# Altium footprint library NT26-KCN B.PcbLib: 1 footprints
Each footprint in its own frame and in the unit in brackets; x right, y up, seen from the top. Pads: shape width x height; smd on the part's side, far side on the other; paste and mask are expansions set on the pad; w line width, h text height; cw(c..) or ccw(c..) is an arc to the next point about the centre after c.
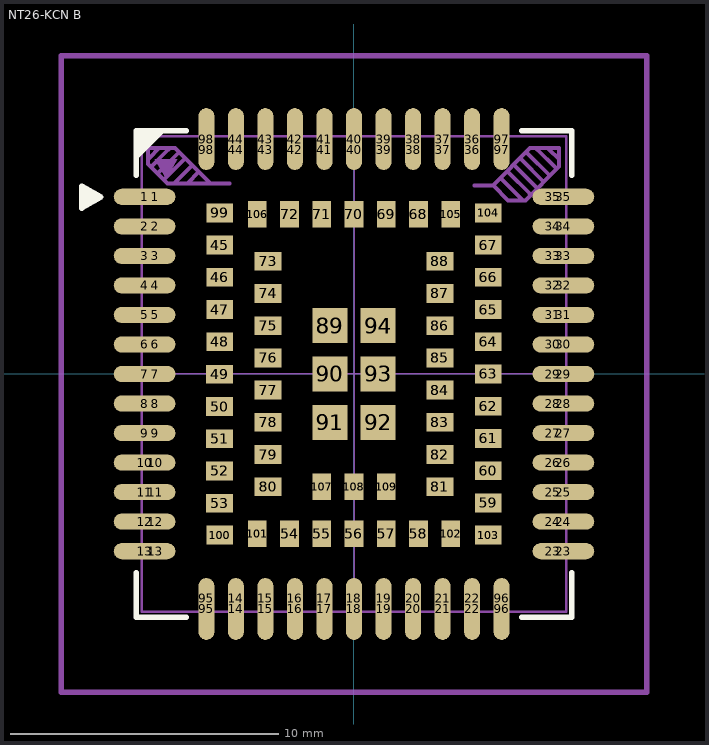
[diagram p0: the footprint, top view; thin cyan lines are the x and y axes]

## NT26-KCN B [mm]
height 2.54
pads (220):
  oval 2.3x0.6 smd mask+0.076: 1(-7.8,6.6) 2(-7.8,5.5) 3(-7.8,4.4) 4(-7.8,3.3) 5(-7.8,2.2) 6(-7.8,1.1) 7(-7.8,0) 8(-7.8,-1.1) 9(-7.8,-2.2) 10(-7.8,-3.3) 11(-7.8,-4.4) 12(-7.8,-5.5) 13(-7.8,-6.6) 23(7.8,-6.6) 24(7.8,-5.5) 25(7.8,-4.4) 26(7.8,-3.3) 27(7.8,-2.2) 28(7.8,-1.1) 29(7.8,0) 30(7.8,1.1) 31(7.8,2.2) 32(7.8,3.3) 33(7.8,4.4) 34(7.8,5.5) 35(7.8,6.6)
  oval 1.5x0.6 on Mech1 mask+0.076: 1(-7.4,6.6) 2(-7.4,5.5) 3(-7.4,4.4) 4(-7.4,3.3) 5(-7.4,2.2) 6(-7.4,1.1) 7(-7.4,0) 8(-7.4,-1.1) 9(-7.4,-2.2) 10(-7.4,-3.3) 11(-7.4,-4.4) 12(-7.4,-5.5) 13(-7.4,-6.6) 23(7.4,-6.6) 24(7.4,-5.5) 25(7.4,-4.4) 26(7.4,-3.3) 27(7.4,-2.2) 28(7.4,-1.1) 29(7.4,0) 30(7.4,1.1) 31(7.4,2.2) 32(7.4,3.3) 33(7.4,4.4) 34(7.4,5.5) 35(7.4,6.6)
  oval 0.6x2.3 smd mask+0.076: 14(-4.4,-8.75) 15(-3.3,-8.75) 16(-2.2,-8.75) 17(-1.1,-8.75) 18(0,-8.75) 19(1.1,-8.75) 20(2.2,-8.75) 21(3.3,-8.75) 22(4.4,-8.75) 36(4.4,8.75) 37(3.3,8.75) 38(2.2,8.75) 39(1.1,8.75) 40(0,8.75) 41(-1.1,8.75) 42(-2.2,8.75) 43(-3.3,8.75) 44(-4.4,8.75) 95(-5.5,-8.75) 96(5.5,-8.75) 97(5.5,8.75) 98(-5.5,8.75)
  oval 0.6x1.5 on Mech1 mask+0.076: 14(-4.4,-8.35) 15(-3.3,-8.35) 16(-2.2,-8.35) 17(-1.1,-8.35) 18(0,-8.35) 19(1.1,-8.35) 20(2.2,-8.35) 21(3.3,-8.35) 22(4.4,-8.35) 36(4.4,8.35) 37(3.3,8.35) 38(2.2,8.35) 39(1.1,8.35) 40(0,8.35) 41(-1.1,8.35) 42(-2.2,8.35) 43(-3.3,8.35) 44(-4.4,8.35) 95(-5.5,-8.35) 96(5.5,-8.35) 97(5.5,8.35) 98(-5.5,8.35)
  rect 1x0.7 smd: 45(-5,4.8) 46(-5,3.6) 47(-5,2.4) 48(-5,1.2) 49(-5.003,-0.011) 50(-5.003,-1.211) 51(-5.003,-2.411) 52(-5.003,-3.611) 53(-5.003,-4.811) 59(5,-4.8) 60(5,-3.6) 61(5,-2.4) 62(5,-1.2) 63(5,0) 64(5,1.2) 65(5,2.4) 66(5,3.6) 67(5,4.8) 73(-3.2,4.2) 74(-3.2,3) 75(-3.2,1.8) 76(-3.2,0.6) 77(-3.2,-0.6) 78(-3.2,-1.8) 79(-3.2,-3) 80(-3.2,-4.2) 81(3.2,-4.2) 82(3.2,-3) 83(3.2,-1.8) 84(3.2,-0.6) 85(3.2,0.6) 86(3.2,1.8) 87(3.2,3) 88(3.2,4.2) 99(-5,6) 100(-5,-6) 103(5,-6) 104(5,6)
  rect 1x0.7 on Mech1: 45(-5,4.8) 46(-5,3.6) 47(-5,2.4) 48(-5,1.2) 49(-5.003,-0.011) 50(-5.003,-1.211) 51(-5.003,-2.411) 52(-5.003,-3.611) 53(-5.003,-4.811) 59(5,-4.8) 60(5,-3.6) 61(5,-2.4) 62(5,-1.2) 63(5,0) 64(5,1.2) 65(5,2.4) 66(5,3.6) 67(5,4.8) 73(-3.2,4.2) 74(-3.2,3) 75(-3.2,1.8) 76(-3.2,0.6) 77(-3.2,-0.6) 78(-3.2,-1.8) 79(-3.2,-3) 80(-3.2,-4.2) 81(3.2,-4.2) 82(3.2,-3) 83(3.2,-1.8) 84(3.2,-0.6) 85(3.2,0.6) 86(3.2,1.8) 87(3.2,3) 88(3.2,4.2) 99(-5,6) 100(-5,-6) 103(5,-6) 104(5,6)
  rect 0.7x1 smd: 54(-2.4,-5.95) 55(-1.2,-5.95) 56(0,-5.95) 57(1.2,-5.95) 58(2.4,-5.95) 68(2.4,5.95) 69(1.2,5.95) 70(0,5.95) 71(-1.2,5.95) 72(-2.4,5.95) 101(-3.6,-5.95) 102(3.6,-5.95) 105(3.6,5.95) 106(-3.6,5.95) 107(-1.2,-4.2) 108(0,-4.2) 109(1.2,-4.2)
  rect 0.7x1 on Mech1: 54(-2.4,-5.95) 55(-1.2,-5.95) 56(0,-5.95) 57(1.2,-5.95) 58(2.4,-5.95) 68(2.4,5.95) 69(1.2,5.95) 70(0,5.95) 71(-1.2,5.95) 72(-2.4,5.95) 101(-3.6,-5.95) 102(3.6,-5.95) 105(3.6,5.95) 106(-3.6,5.95) 107(-1.2,-4.2) 108(0,-4.2) 109(1.2,-4.2)
  rect 1.3x1.3 smd: 89(-0.9,1.8) 90(-0.9,0) 91(-0.9,-1.8) 92(0.9,-1.8) 93(0.9,0) 94(0.9,1.8)
  rect 1.3x1.3 on Mech1: 89(-0.9,1.8) 90(-0.9,0) 91(-0.9,-1.8) 92(0.9,-1.8) 93(0.9,0) 94(0.9,1.8)
  round 0.8 on Mech1: ""(5.85,6.95) ""(6.95,7.95)
Top Overlay:
  region: -10.144,6.175 -9.42,6.59 -10.144,7.002
  region: -8.108,9.057 -8.097,7.973 -7.023,9.047
  lines w0.199: -8.108,-7.406 -8.108,-9.057 -6.25,-9.057 ; -8.108,7.406 -8.108,9.057 -6.25,9.057 ; 6.25,-9.057 8.108,-9.057 8.108,-7.406 ; 6.25,9.057 8.108,9.057 8.108,7.406 ; -10.144,6.175 -10.144,7.002 -9.42,6.59 -10.144,6.175
Mechanical 1:
  region: -7.415,7.992 -7,7.268 -6.589,7.992
  lines w0.051: -7.9,0 7.9,0 ; 0,-8.85 0,8.85
  lines w0.1: -7.9,-8.85 7.9,-8.85 7.9,8.85 -7.9,8.85 -7.9,-8.85
  lines w0.149: -7.62,8.05 -7.26,8.41 ; -7.55,7.73 -6.91,8.37 ; -7.295,7.485 -6.54,8.24 ; -7.075,7.235 -6.31,8 ; -6.675,7.125 -6.07,7.73 ; -6.17,7.14 -5.81,7.5 ; -4.9,7.1 -6.95,7.1 -7.67,7.82 -7.67,8.41 -6.66,8.41 -5.35,7.1 -4.89,7.1 -4.63,7.1 ; 4.49,7.02 5.19,7.02 5.74,6.47 6.38,6.47 7.64,7.73 7.64,8.41 6.56,8.41 5.17,7.02 ; 5.49,7.26 6.275,6.475 ; 5.74,7.52 6.545,6.715 ; 6,7.75 6.82,6.93 ; 6.22,8 7.06,7.16 ; 6.47,8.21 7.29,7.39 ; 6.81,8.37 7.515,7.665 ; 7.27,8.36 7.63,8
  lines w0.199: -10.9,-11.85 -9.9,-11.85 9.9,-11.85 10.9,-11.85 10.9,-10.85 10.9,10.85 10.9,11.85 9.9,11.85 -5.5,11.85 -9.9,11.85 -10.9,11.85 -10.9,10.85 -10.9,-10.85 -10.9,-11.85
  text "TOP层禁止布线区域" at -4.45,6.57 h1.2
